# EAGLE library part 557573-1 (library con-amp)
AMP connector
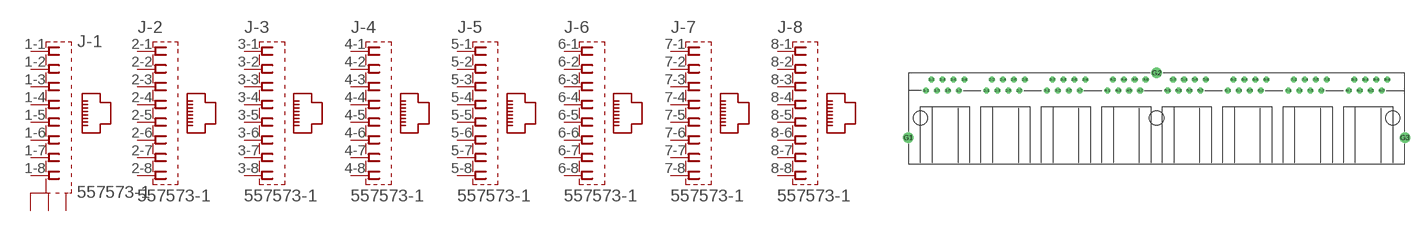
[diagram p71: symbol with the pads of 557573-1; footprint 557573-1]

Designator prefix J; gates -1=JACK8SH3 -2=JACK8_SH -3=JACK8_SH -4=JACK8_SH -5=JACK8_SH -6=JACK8_SH -7=JACK8_SH -8=JACK8_SH

## 557573-1 (MPN: 557573-1; OC_FARNELL: unknown; OC_NEWARK: 97F9563)  [557573-1]
1-1  -1:1  pas
1-2  -1:2  pas
1-3  -1:3  pas
1-4  -1:4  pas
1-5  -1:5  pas
1-6  -1:6  pas
1-7  -1:7  pas
1-8  -1:8  pas
2-1  -2:1  pas
2-2  -2:2  pas
2-3  -2:3  pas
2-4  -2:4  pas
2-5  -2:5  pas
2-6  -2:6  pas
2-7  -2:7  pas
2-8  -2:8  pas
3-1  -3:1  pas
3-2  -3:2  pas
3-3  -3:3  pas
3-4  -3:4  pas
3-5  -3:5  pas
3-6  -3:6  pas
3-7  -3:7  pas
3-8  -3:8  pas
4-1  -4:1  pas
4-2  -4:2  pas
4-3  -4:3  pas
4-4  -4:4  pas
4-5  -4:5  pas
4-6  -4:6  pas
4-7  -4:7  pas
4-8  -4:8  pas
5-1  -5:1  pas
5-2  -5:2  pas
5-3  -5:3  pas
5-4  -5:4  pas
5-5  -5:5  pas
5-6  -5:6  pas
5-7  -5:7  pas
5-8  -5:8  pas
6-1  -6:1  pas
6-2  -6:2  pas
6-3  -6:3  pas
6-4  -6:4  pas
6-5  -6:5  pas
6-6  -6:6  pas
6-7  -6:7  pas
6-8  -6:8  pas
7-1  -7:1  pas
7-2  -7:2  pas
7-3  -7:3  pas
7-4  -7:4  pas
7-5  -7:5  pas
7-6  -7:6  pas
7-7  -7:7  pas
7-8  -7:8  pas
8-1  -8:1  pas
8-2  -8:2  pas
8-3  -8:3  pas
8-4  -8:4  pas
8-5  -8:5  pas
8-6  -8:6  pas
8-7  -8:7  pas
8-8  -8:8  pas
G1  -1:9  pas
G2  -1:10  pas
G3  -1:11  pas

## Footprint 557573-1 (pad centres in mm)
Modular Jack Shielded
drill 0.889 round: 1-1 -53.34,6.35; 1-2 -52.07,8.89; 1-3 -50.8,6.35; 1-4 -49.53,8.89; 1-5 -48.26,6.35; 1-6 -46.99,8.89; 1-7 -45.72,6.35; 1-8 -44.45,8.89; 2-1 -39.37,6.35; 2-2 -38.1,8.89; 2-3 -36.83,6.35; 2-4 -35.56,8.89; 2-5 -34.29,6.35; 2-6 -33.02,8.89; 2-7 -31.75,6.35; 2-8 -30.48,8.89; 3-1 -25.4,6.35; 3-2 -24.13,8.89; 3-3 -22.86,6.35; 3-4 -21.59,8.89; 3-5 -20.32,6.35; 3-6 -19.05,8.89; 3-7 -17.78,6.35; 3-8 -16.51,8.89; 4-1 -11.43,6.35; 4-2 -10.16,8.89; 4-3 -8.89,6.35; 4-4 -7.62,8.89; 4-5 -6.35,6.35; 4-6 -5.08,8.89; 4-7 -3.81,6.35; 4-8 -2.54,8.89; 5-1 2.54,6.35; 5-2 3.81,8.89; 5-3 5.08,6.35; 5-4 6.35,8.89; 5-5 7.62,6.35; 5-6 8.89,8.89; 5-7 10.16,6.35; 5-8 11.43,8.89; 6-1 16.51,6.35; 6-2 17.78,8.89; 6-3 19.05,6.35; 6-4 20.32,8.89; 6-5 21.59,6.35; 6-6 22.86,8.89; 6-7 24.13,6.35; 6-8 25.4,8.89; 7-1 30.48,6.35; 7-2 31.75,8.89; 7-3 33.02,6.35; 7-4 34.29,8.89; 7-5 35.56,6.35; 7-6 36.83,8.89; 7-7 38.1,6.35; 7-8 39.37,8.89; 8-1 44.45,6.35; 8-2 45.72,8.89; 8-3 46.99,6.35; 8-4 48.26,8.89; 8-5 49.53,6.35; 8-6 50.8,8.89; 8-7 52.07,6.35; 8-8 53.34,8.89
drill 1.575 pad 2.184 round: G1 -57.404,-4.572; G2 0,10.414; G3 57.404,-4.572
hole 3.251 at -54.61,0
hole 3.251 at 54.61,0
hole 3.251 at 0,0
